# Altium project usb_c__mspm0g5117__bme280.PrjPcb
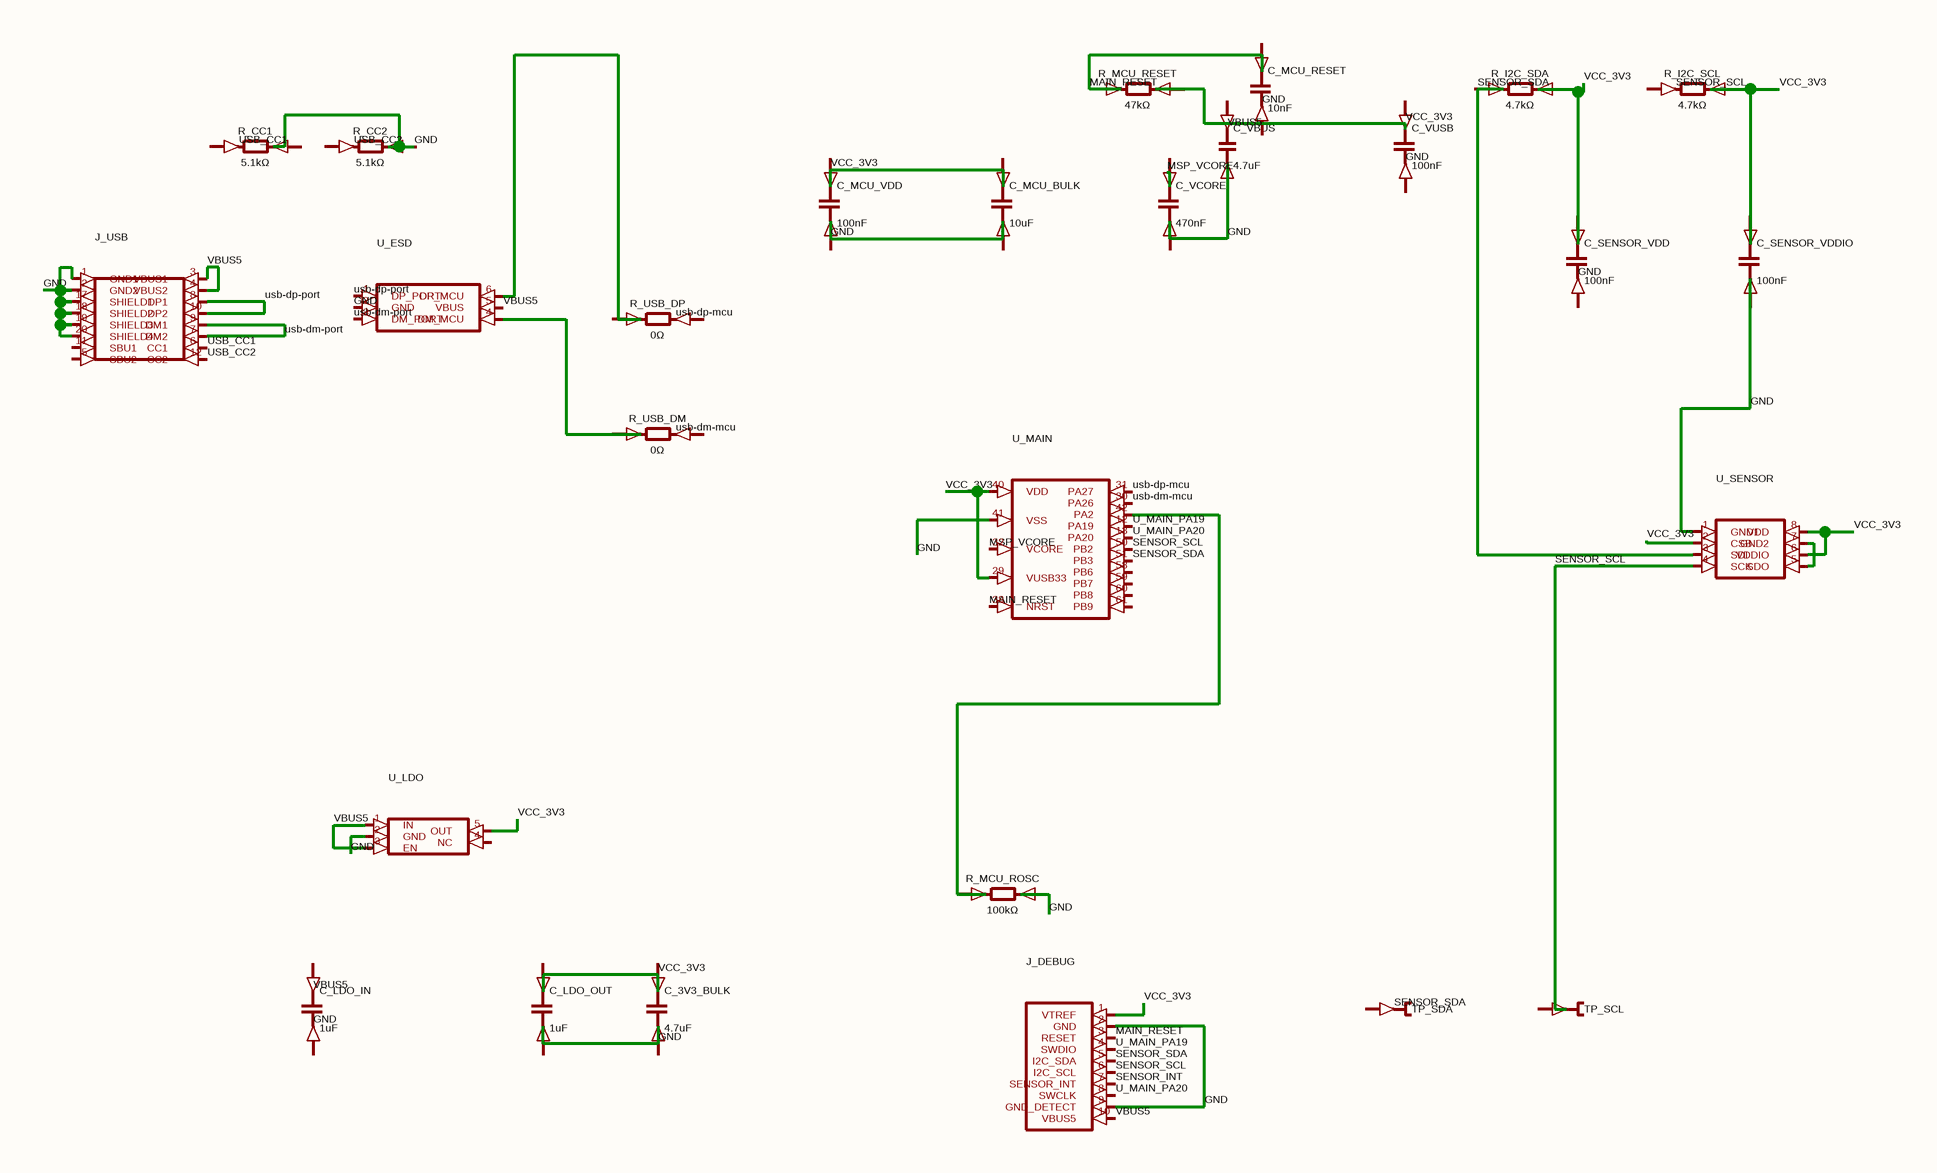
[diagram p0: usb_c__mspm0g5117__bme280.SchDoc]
1 sheet, 27 parts. Net scope: global (net labels, ports and power ports of the same name join across sheets).
Board file: usb_c__mspm0g5117__bme280.PcbDoc

## Sheet usb_c__mspm0g5117__bme280.SchDoc
size 210 x 144 mm

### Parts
C_3V3_BULK  4.7uF
C_LDO_IN  1uF
C_LDO_OUT  1uF
C_MCU_BULK  10uF
C_MCU_RESET  10nF
C_MCU_VDD  100nF
C_SENSOR_VDD  100nF
C_SENSOR_VDDIO  100nF
C_VBUS  4.7uF
C_VCORE  470nF
C_VUSB  100nF
J_DEBUG  (no value)
J_USB  (no value)
R_CC1  5.1kΩ
R_CC2  5.1kΩ
R_I2C_SCL  4.7kΩ
R_I2C_SDA  4.7kΩ
R_MCU_RESET  47kΩ
R_MCU_ROSC  100kΩ
R_USB_DM  0Ω
R_USB_DP  0Ω
TP_SCL  (no value)
TP_SDA  (no value)
U_ESD  (no value)
U_LDO  (no value)
U_MAIN  (no value)
U_SENSOR  (no value)

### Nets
GND: C_SENSOR_VDD.1(anode) C_SENSOR_VDDIO.1(anode) C_SENSOR_VDDIO.2(cathode) C_VBUS.2(cathode) J_DEBUG.1(VTREF) J_DEBUG.2(GND) J_DEBUG.9(GND_DETECT) J_DEBUG.10(VBUS5) J_USB.1(GND1) J_USB.2(GND2) J_USB.3(VBUS1) J_USB.4(VBUS2) J_USB.17(SHIELD1) J_USB.18(SHIELD2) J_USB.19(SHIELD3) J_USB.20(SHIELD4) R_I2C_SCL.2(cathode) R_I2C_SDA.2(cathode) R_MCU_RESET.2(cathode) R_MCU_ROSC.2(cathode) U_ESD.2(GND) U_ESD.5(VBUS) U_LDO.1(IN) U_LDO.2(GND) U_LDO.3(EN) U_LDO.5(OUT) U_MAIN.29(VUSB33) U_MAIN.40(VDD) U_MAIN.41(VSS) U_SENSOR.1(GND1) U_SENSOR.2(CSB) U_SENSOR.5(SDO) U_SENSOR.6(VDDIO) U_SENSOR.7(GND2) U_SENSOR.8(VDD)  [also labelled VBUS5, VCC_3V3]
MAIN_RESET: J_DEBUG.3(RESET) R_MCU_RESET.1(anode) U_MAIN.38(NRST)
MSP_VCORE: U_MAIN.32(VCORE)
SENSOR_INT: J_DEBUG.7(SENSOR_INT)
SENSOR_SCL: J_DEBUG.6(I2C_SCL) U_MAIN.50(PB2) U_SENSOR.4(SCK)
SENSOR_SDA: J_DEBUG.5(I2C_SDA) U_MAIN.51(PB3) U_SENSOR.3(SDI)
U_MAIN_PA19: J_DEBUG.4(SWDIO) U_MAIN.12(PA19)
U_MAIN_PA20: J_DEBUG.8(SWCLK) U_MAIN.13(PA20)
usb-dm-mcu: U_MAIN.30(PA26)
usb-dm-port: J_USB.7(DM2) J_USB.9(DM1) U_ESD.3(DM_PORT)
usb-dp-mcu: U_MAIN.31(PA27)
usb-dp-port: J_USB.8(DP1) J_USB.10(DP2) U_ESD.1(DP_PORT)
USB_CC1: J_USB.6(CC1)
USB_CC2: J_USB.12(CC2)
NetR_MCU_ROSC_1: R_MCU_ROSC.1(anode) U_MAIN.42(PA2)
NetR_USB_DM_1: R_USB_DM.1(anode) U_ESD.4(DM_MCU)

Not connected (* = marked no-connect by the designer): C_3V3_BULK 1(anode) 2(cathode); C_LDO_IN 1(anode) 2(cathode); C_LDO_OUT 1(anode) 2(cathode); C_MCU_BULK 1(anode) 2(cathode); C_MCU_RESET 1(anode) 2(cathode); C_MCU_VDD 1(anode) 2(cathode); C_SENSOR_VDD 2(cathode); C_VBUS 1(anode); C_VCORE 1(anode) 2(cathode); C_VUSB 1(anode) 2(cathode); J_USB 5(SBU2) 11(SBU1); R_CC1 1(anode) 2(cathode); R_CC2 1(anode) 2(cathode); R_I2C_SCL 1(anode); R_I2C_SDA 1(anode); R_USB_DM 2(cathode); R_USB_DP 1(anode) 2(cathode); TP_SCL 1(pin1); TP_SDA 1(pin1); U_ESD 6(DP_MCU); U_LDO 4(NC); U_MAIN 58(PB6) 59(PB7) 60(PB8) 61(PB9)

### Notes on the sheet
- Labels drawn without touching a wire or pin: GND, SENSOR_SCL, SENSOR_SDA, usb-dm-mcu, usb-dp-mcu, USB_CC1, USB_CC2, VBUS5

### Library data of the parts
C_3V3_BULK C_LDO_IN C_LDO_OUT C_MCU_BULK C_MCU_RESET C_MCU_VDD C_SENSOR_VDD C_SENSOR_VDDIO C_VBUS C_VCORE C_VUSB = capacitor_down
J_DEBUG = J_DEBUG
J_USB = J_USB
R_CC1 R_CC2 R_I2C_SCL R_I2C_SDA R_MCU_RESET R_MCU_ROSC R_USB_DM R_USB_DP = boxresistor_right
TP_SCL TP_SDA = testpoint_right
U_ESD = U_ESD
U_LDO = U_LDO
U_MAIN = U_MAIN
U_SENSOR = U_SENSOR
